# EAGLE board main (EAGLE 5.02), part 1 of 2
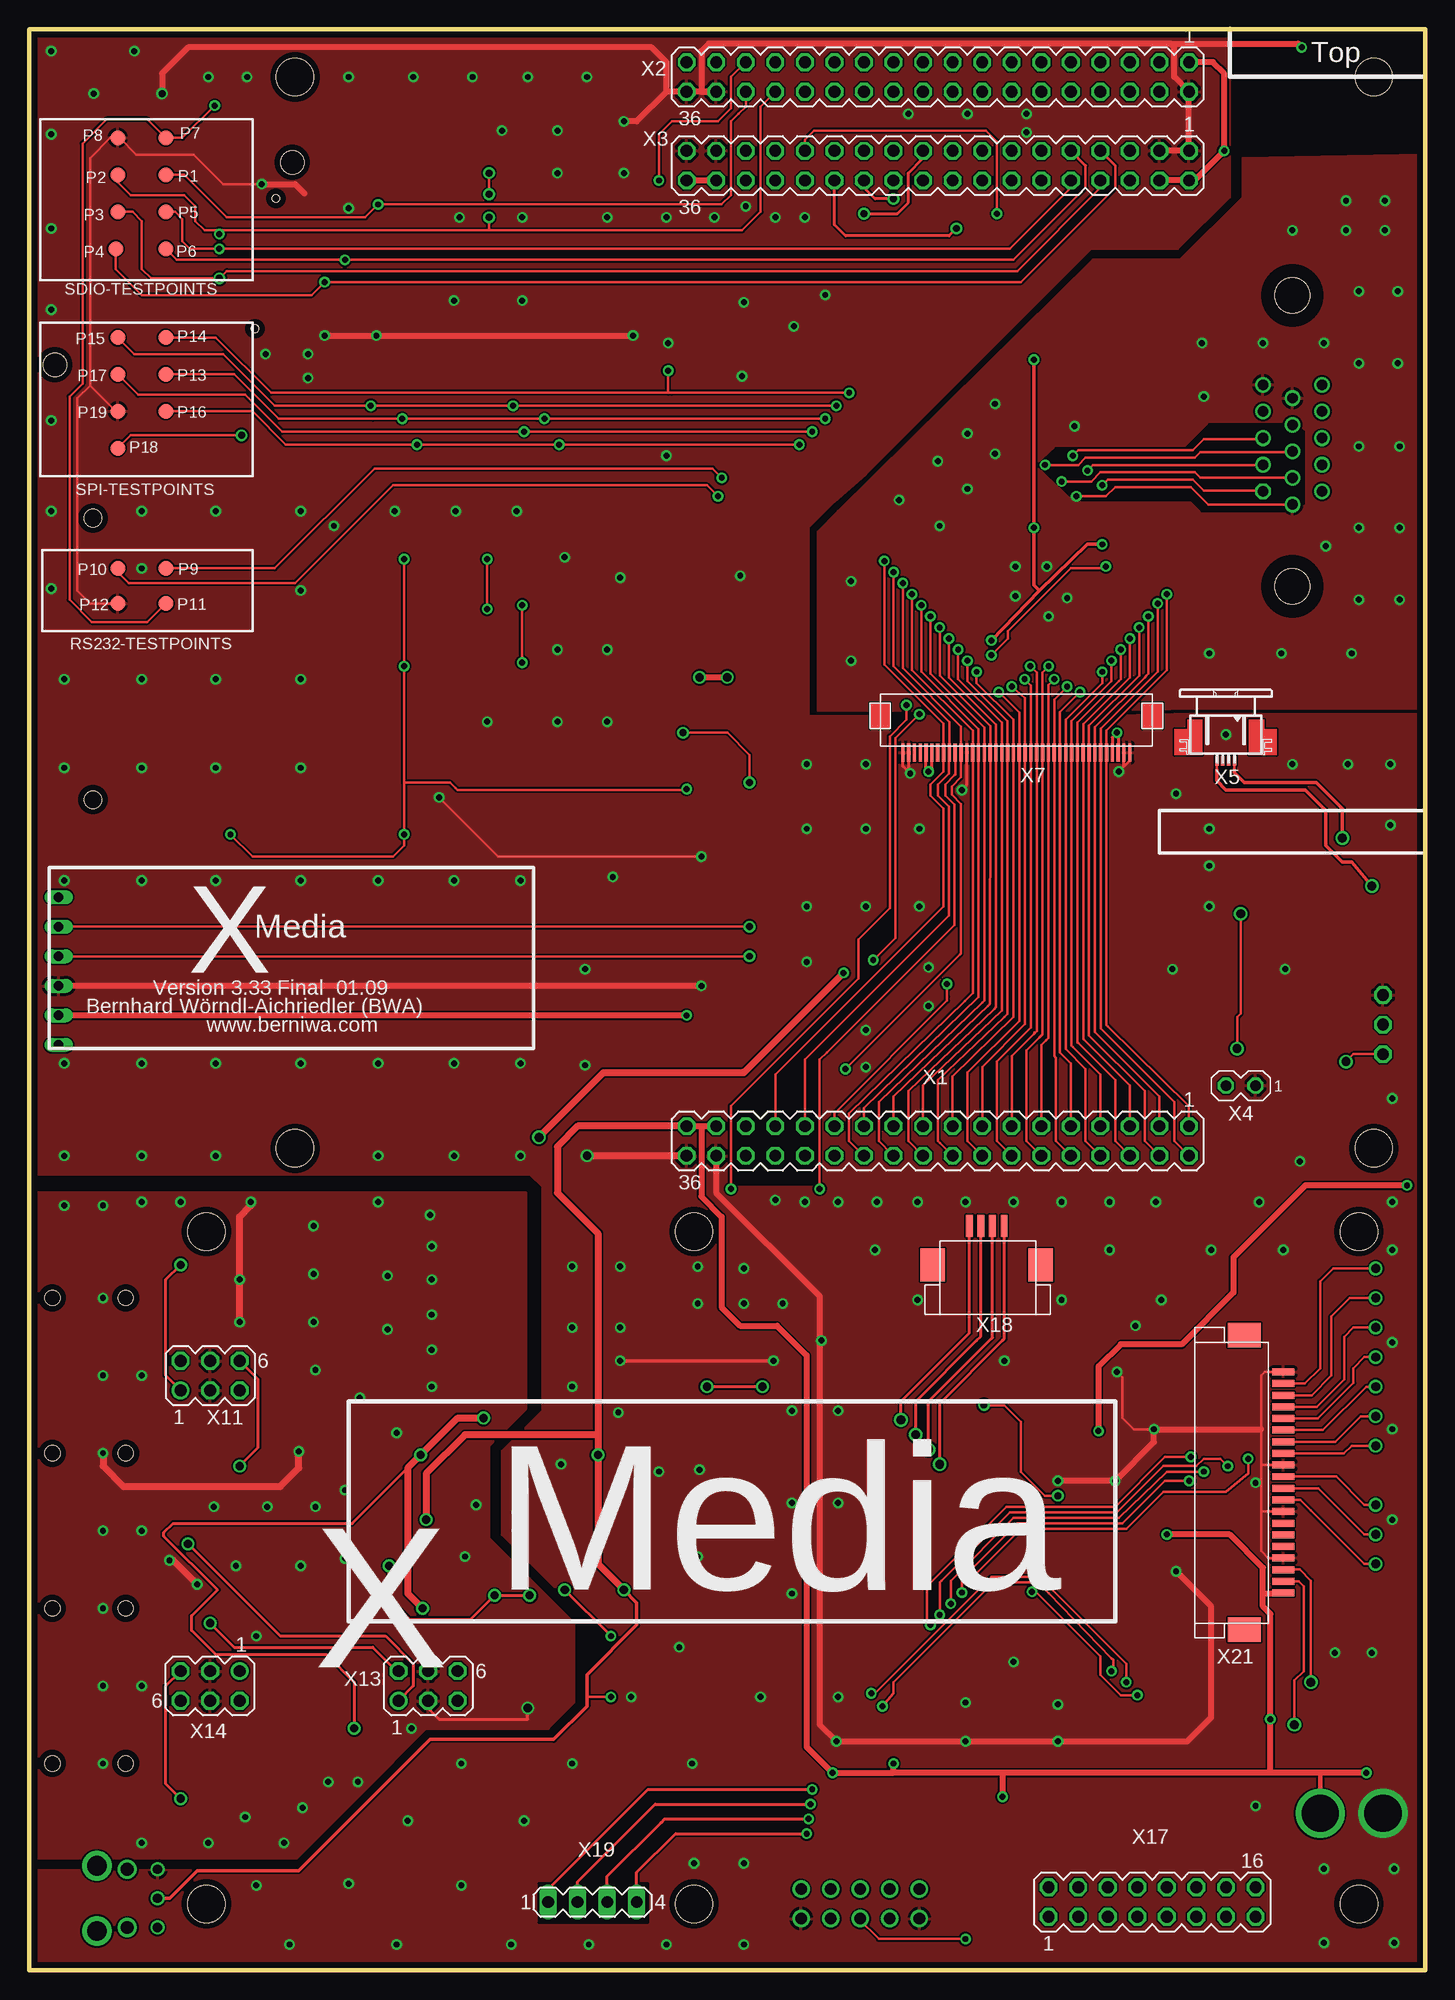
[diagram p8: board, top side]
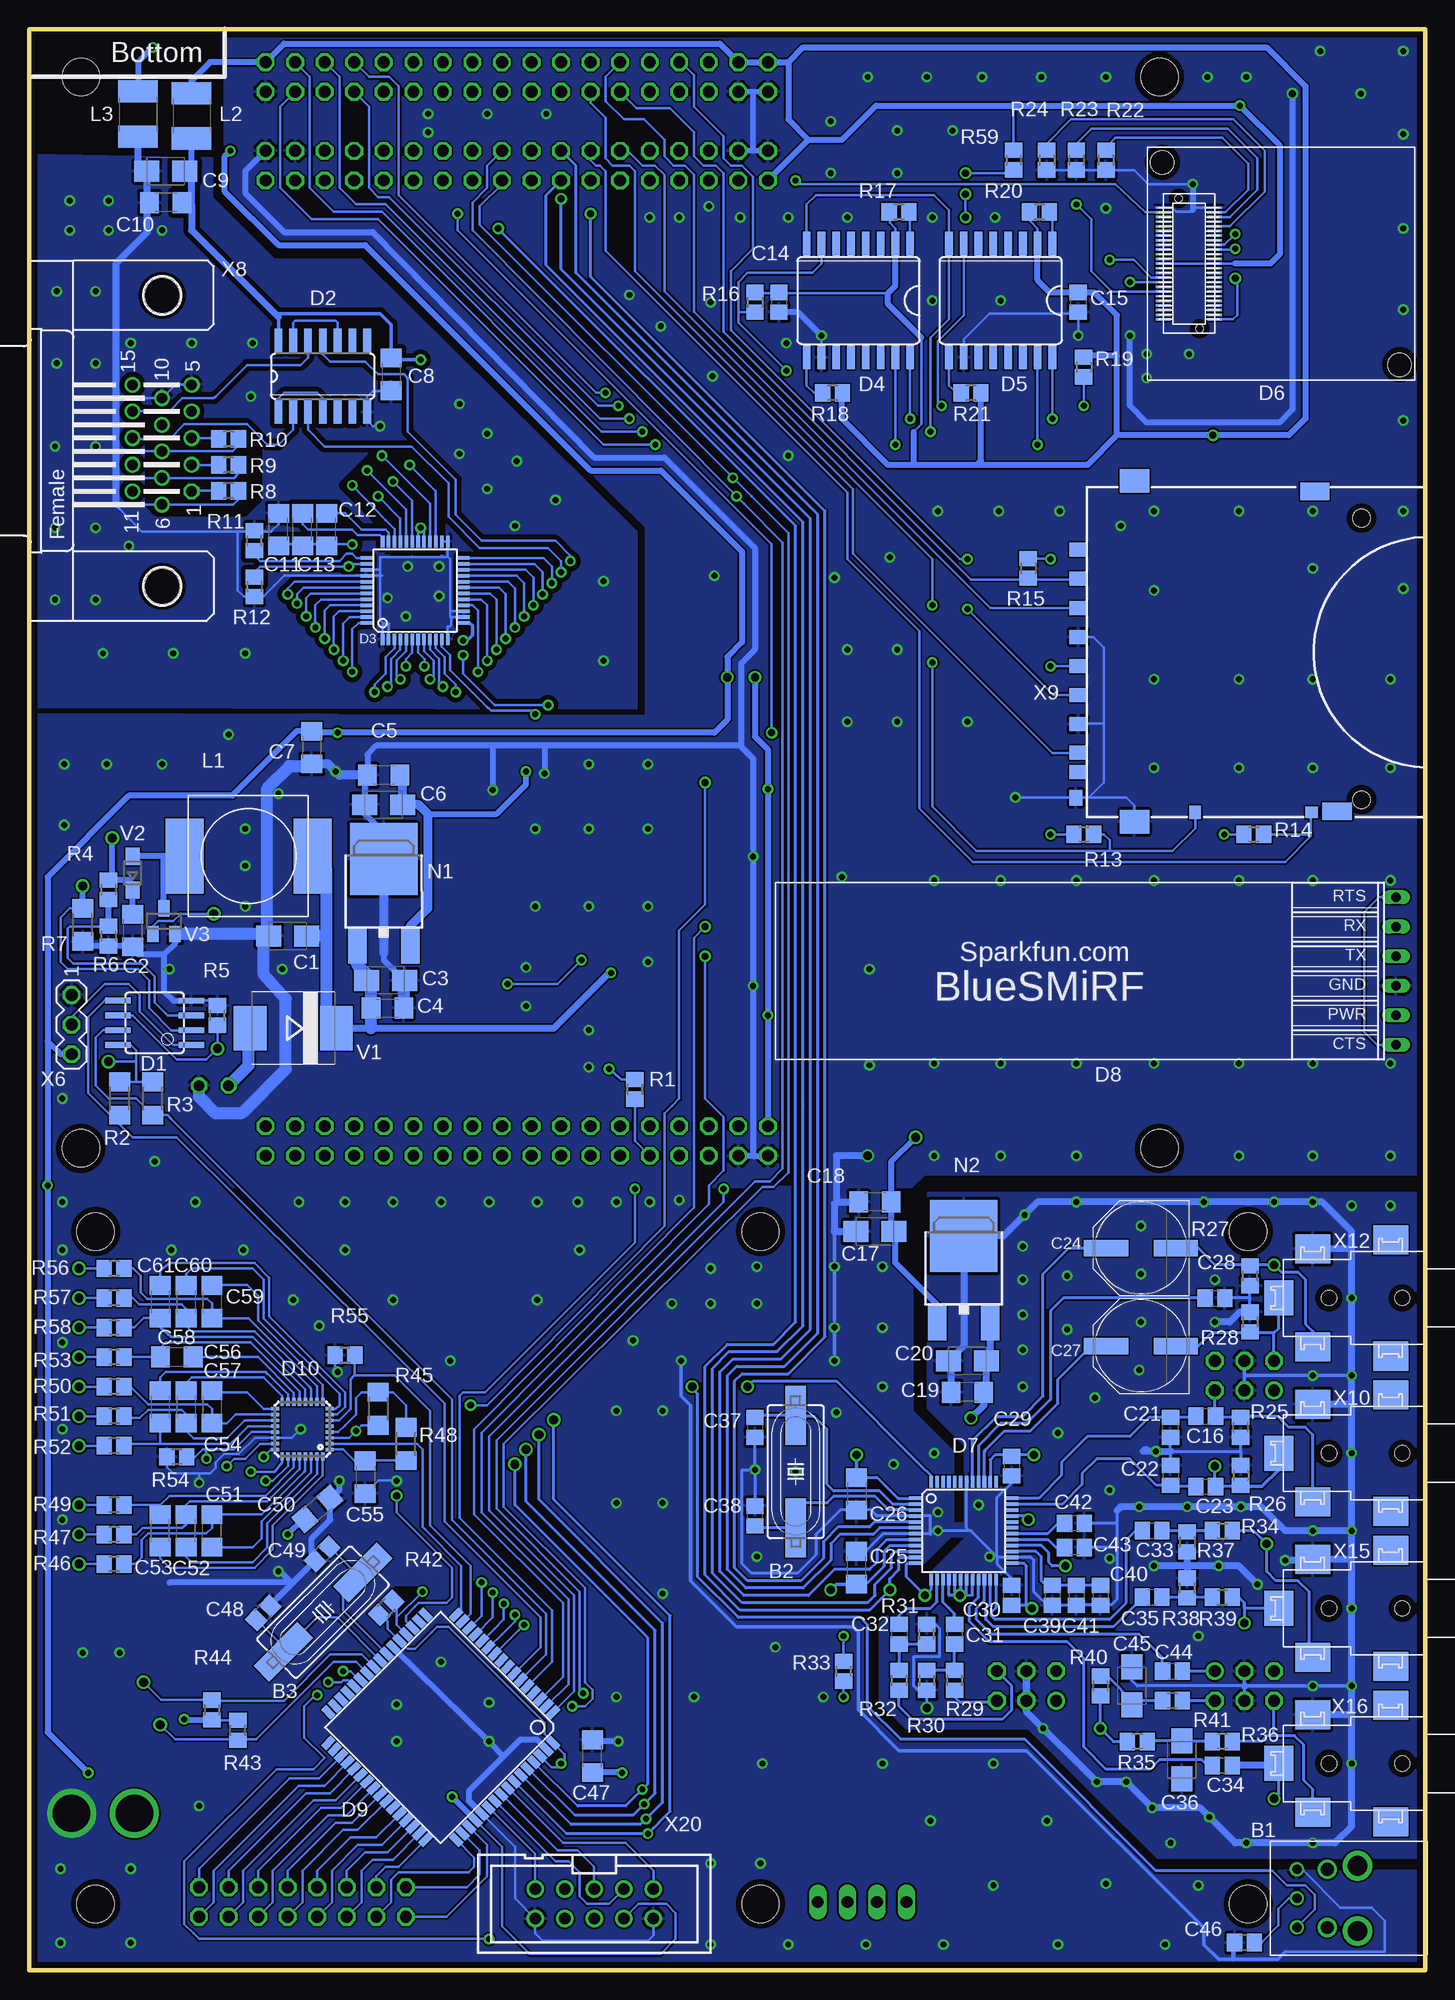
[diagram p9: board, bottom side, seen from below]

Size 120.02 x 166.83 mm. Coordinates in mm from the lower left corner, seen from the top.
Outline: 120,64.77 120,166.83 0,166.83 0,0 120.02,0 120.02,64.77
Copper layers (1+16): Top 0.035mm / dielectric 1.6mm / Bottom 0.035mm
Design rules "microtec *": minimum track width 6mil, minimum drill 0.4mm, track to track 6mil, track to pad 6mil, pad to pad 6mil, via to via 6mil, smd to smd 6mil, copper to edge 20mil, drill to drill 10mil, minimum pad ring 8mil, minimum via ring 8mil, stop-mask expansion 4mil, vias tented up to drill 18mil, thermal gap 10mil
Holes 3.2 mm at 115.57,162.72 22.86,162.72 22.86,70.64 115.57,70.64 15.24,63.5 15.24,5.71 114.3,63.5 114.3,5.71 57.15,5.71 57.15,63.5
tRestrict: area 43.8,4.1 to 53.2,7.5; area 86.7,125.4 to 109.5,132.9
bRestrict: area 86.4,31.7 to 88.6,32.9; area 100.5,125.4 to 109.5,132.9; area 84.8,121.4 to 92.9,130.7

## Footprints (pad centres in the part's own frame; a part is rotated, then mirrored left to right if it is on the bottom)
TOTX147PL = drill 0.8 round: 1 -2.5,-11.2; 2 0,-11.2; 3 2.5,-11.2 | drill 1.7 round: NC1 -2.8,-6; NC2 2.8,-6 | drill 1.1 round: NC3 -2.5,-8.6; NC4 2.5,-8.6
SM49 = smd 5.08 x 1.778: 1 -4.826,0; 2 4.826,0
HC49UP = smd 5.334 x 1.93: 1 -4.826,0; 2 4.826,0
B/3528-21W = smd 2.15 x 1.8: + 1.625,0; - -1.625,0
C1206 = smd 1.6 x 1.8: 1 -1.4,0; 2 1.4,0
C0805 = smd 1.3 x 1.5: 1 -0.85,0; 2 0.85,0
PANASONIC_E = smd 3.8 x 1.4: + 3,0; - -3,0
SOIC8 = smd 0.5 x 2.2: 1 -1.905,-3.154; 2 -0.645,-3.154; 3 0.625,-3.154; 4 1.895,-3.154; 5 1.905,3.154; 6 0.635,3.154; 7 -0.635,3.154; 8 -1.905,3.154
SO14 = smd 0.66 x 2.032: 1 -3.81,-3.073; 2 -2.54,-3.073; 3 -1.27,-3.073; 4 0,-3.073; 5 1.27,-3.073; 6 2.54,-3.073; 7 3.81,-3.073; 8 3.81,3.073; 9 2.54,3.073; 10 1.27,3.073; 11 0,3.073; 12 -1.27,3.073; 13 -2.54,3.073; 14 -3.81,3.073
TQFP48 = smd 1.016 x 0.305: 1 -4.191,2.794; 2 -4.191,2.286; 3 -4.191,1.778; 4 -4.191,1.27; 5 -4.191,0.762; 6 -4.191,0.254; 7 -4.191,-0.254; 8 -4.191,-0.762; 9 -4.191,-1.27; 10 -4.191,-1.778; 11 -4.191,-2.286; 12 -4.191,-2.794; 25 4.191,-2.794; 26 4.191,-2.286; 27 4.191,-1.778; 28 4.191,-1.27; 29 4.191,-0.762; 30 4.191,-0.254; 31 4.191,0.254; 32 4.191,0.762; 33 4.191,1.27; 34 4.191,1.778; 35 4.191,2.286; 36 4.191,2.794 | smd 0.305 x 1.016: 13 -2.794,-4.191; 14 -2.286,-4.191; 15 -1.778,-4.191; 16 -1.27,-4.191; 17 -0.762,-4.191; 18 -0.254,-4.191; 19 0.254,-4.191; 20 0.762,-4.191; 21 1.27,-4.191; 22 1.778,-4.191; 23 2.286,-4.191; 24 2.794,-4.191; 37 2.794,4.191; 38 2.286,4.191; 39 1.778,4.191; 40 1.27,4.191; 41 0.762,4.191; 42 0.254,4.191; 43 -0.254,4.191; 44 -0.762,4.191; 45 -1.27,4.191; 46 -1.778,4.191; 47 -2.286,4.191; 48 -2.794,4.191
SO16L = smd 0.66 x 2.032: 1 -4.445,-4.902; 2 -3.175,-4.902; 3 -1.905,-4.902; 4 -0.635,-4.902; 5 0.635,-4.902; 6 1.905,-4.902; 7 3.175,-4.902; 8 4.445,-4.902; 9 4.445,4.902; 10 3.175,4.902; 11 1.905,4.902; 12 0.635,4.902; 13 -0.635,4.902; 14 -1.905,4.902; 15 -3.175,4.902; 16 -4.445,4.902
XG-182M = smd 0.203 x 1.27: P$1 4.8,-2.2; P$2 4.4,-2.2; P$3 4,-2.2; P$4 3.6,-2.2; P$5 3.2,-2.2; P$6 2.8,-2.2; P$7 2.4,-2.2; P$8 2,-2.2; P$9 1.6,-2.2; P$10 1.2,-2.2; P$11 0.8,-2.2; P$12 0.4,-2.2; P$13 0,-2.2; P$14 -0.4,-2.2; P$15 -0.8,-2.2; P$16 -1.2,-2.2; P$17 -1.6,-2.2; P$18 -2,-2.2; P$19 -2.4,-2.2; P$20 -2.8,-2.2; P$21 -3.2,-2.2; P$22 -3.6,-2.2; P$23 -4,-2.2; P$24 -4.4,-2.2; P$25 -4.8,-2.2; P$26 -4.8,2.2; P$27 -4.4,2.2; P$28 -4,2.2; P$29 -3.6,2.2; P$30 -3.2,2.2; P$31 -2.8,2.2; P$32 -2.4,2.2; P$33 -2,2.2; P$34 -1.6,2.2; P$35 -1.2,2.2; P$36 -0.8,2.2; P$37 -0.4,2.2; P$38 0,2.2; P$39 0.4,2.2; P$40 0.8,2.2; P$41 1.2,2.2; P$42 1.6,2.2; P$43 2,2.2; P$44 2.4,2.2; P$45 2.8,2.2; P$46 3.2,2.2; P$47 3.6,2.2; P$48 4,2.2; P$49 4.4,2.2; P$50 4.8,2.2 | hole 0.65: 5.6,0.9; -5.6,-0.9 | hole 2: -8.7,-18.1; 8.7,2.3
BLUE_SMIRF_SOCKET = drill 0.813 long: CTS -6.35,-8.89; GND -1.27,-8.89; PWR -3.81,-8.89; RTS 6.35,-8.89; RX 3.81,-8.89; TX 1.27,-8.89
TQFP64 = smd 1.194 x 0.61: 1 -7.76,5.905; 2 -7.76,5.118; 3 -7.76,4.331; 4 -7.76,3.543; 5 -7.76,2.756; 6 -7.76,1.968; 7 -7.76,1.181; 8 -7.76,0.394; 9 -7.76,-0.394; 10 -7.76,-1.181; 11 -7.76,-1.968; 12 -7.76,-2.756; 13 -7.76,-3.543; 14 -7.76,-4.331; 15 -7.76,-5.118; 16 -7.76,-5.905; 33 7.76,-5.905; 34 7.76,-5.118; 35 7.76,-4.331; 36 7.76,-3.543; 37 7.76,-2.756; 38 7.76,-1.968; 39 7.76,-1.181; 40 7.76,-0.394; 41 7.76,0.394; 42 7.76,1.181; 43 7.76,1.968; 44 7.76,2.756; 45 7.76,3.543; 46 7.76,4.331; 47 7.76,5.118; 48 7.76,5.905 | smd 0.61 x 1.194: 17 -5.905,-7.76; 18 -5.118,-7.76; 19 -4.331,-7.76; 20 -3.543,-7.76; 21 -2.756,-7.76; 22 -1.968,-7.76; 23 -1.181,-7.76; 24 -0.394,-7.76; 25 0.394,-7.76; 26 1.181,-7.76; 27 1.968,-7.76; 28 2.756,-7.76; 29 3.543,-7.76; 30 4.331,-7.76; 31 5.118,-7.76; 32 5.905,-7.76; 49 5.905,7.76; 50 5.118,7.76; 51 4.331,7.76; 52 3.543,7.76; 53 2.756,7.76; 54 1.968,7.76; 55 1.181,7.76; 56 0.394,7.76; 57 -0.394,7.76; 58 -1.181,7.76; 59 -1.968,7.76; 60 -2.756,7.76; 61 -3.543,7.76; 62 -4.331,7.76; 63 -5.118,7.76; 64 -5.905,7.76
MLF32 = smd 0.7 x 0.29: 1 -2.35,1.75; 2 -2.35,1.25; 3 -2.35,0.75; 4 -2.35,0.25; 5 -2.35,-0.25; 6 -2.35,-0.75; 7 -2.35,-1.25; 8 -2.35,-1.75; 17 2.35,-1.75; 18 2.35,-1.25; 19 2.35,-0.75; 20 2.35,-0.25; 21 2.35,0.25; 22 2.35,0.75; 23 2.35,1.25; 24 2.35,1.75 | smd 0.29 x 0.7: 9 -1.75,-2.35; 10 -1.25,-2.35; 11 -0.75,-2.35; 12 -0.25,-2.35; 13 0.25,-2.35; 14 0.75,-2.35; 15 1.25,-2.35; 16 1.75,-2.35; 25 1.75,2.35; 26 1.25,2.35; 27 0.75,2.35; 28 0.25,2.35; 29 -0.25,2.35; 30 -0.75,2.35; 31 -1.25,2.35; 32 -1.75,2.35
EPCOS10X10 = smd 3.251 x 6.452: P$1 -0.4,5.2; P$2 10.6,5.2
L1812 = smd 1.9 x 3.4: 1 -1.95,0; 2 1.95,0
DPAK = smd 1.6 x 3: 1 -2.28,-4.04; 3 2.28,-4.04 | smd 5.791 x 6.198: 4 0,3.427
B1,27 = smd 1.27 x 1.27: PP 0,0
R0805 = smd 1.3 x 1.5: 1 -0.85,0; 2 0.85,0
R1206 = smd 1.6 x 1.803: 1 -1.422,0; 2 1.422,0
SMC = smd 2.8 x 3.8: A 3.7,0; C -3.7,0
SOD323-W = smd 1.5 x 1.2: A 1.45,0; C -1.45,0
SOT23 = smd 1 x 1.4: 1 -0.95,-1.1; 2 0.95,-1.1; 3 0,1.1
MA18-2 = drill 1.016 octagon: 1 -21.59,-1.27; 2 -21.59,1.27; 3 -19.05,-1.27; 4 -19.05,1.27; 5 -16.51,-1.27; 6 -16.51,1.27; 7 -13.97,-1.27; 8 -13.97,1.27; 9 -11.43,-1.27; 10 -11.43,1.27; 11 -8.89,-1.27; 12 -8.89,1.27; 13 -6.35,-1.27; 14 -6.35,1.27; 15 -3.81,-1.27; 16 -3.81,1.27; 17 -1.27,-1.27; 18 -1.27,1.27; 19 1.27,-1.27; 20 1.27,1.27; 21 3.81,-1.27; 22 3.81,1.27; 23 6.35,-1.27; 24 6.35,1.27; 25 8.89,-1.27; 26 8.89,1.27; 27 11.43,-1.27; 28 11.43,1.27; 29 13.97,-1.27; 30 13.97,1.27; 31 16.51,-1.27; 32 16.51,1.27; 33 19.05,-1.27; 34 19.05,1.27; 35 21.59,-1.27; 36 21.59,1.27
02P = drill 0.914 octagon: 1 -1.27,0; 2 1.27,0
52745-0490 = smd 0.3 x 0.8: 1 0.52,-0.04; 2 1.02,-0.04; 3 1.52,-0.04; 4 2.02,-0.04
MA03-1 = drill 1.016 octagon: 1 -2.54,0; 2 0,0; 3 2.54,0
ZIF40 = smd 0.279 x 1.524: 1 0.25,0.75; 2 0.75,0.75; 3 1.25,0.75; 4 1.75,0.75; 5 2.25,0.75; 6 2.75,0.75; 7 3.25,0.75; 8 3.75,0.75; 9 4.25,0.75; 10 4.75,0.75; 11 5.25,0.75; 12 5.75,0.75; 13 6.25,0.75; 14 6.75,0.75; 15 7.25,0.75; 16 7.75,0.75; 17 8.25,0.75; 18 8.75,0.75; 19 9.25,0.75; 20 9.75,0.75; 21 10.25,0.75; 22 10.75,0.75; 23 11.25,0.75; 24 11.75,0.75; 25 12.25,0.75; 26 12.75,0.75; 27 13.25,0.75; 28 13.75,0.75; 29 14.25,0.75; 30 14.75,0.75; 31 15.25,0.75; 32 15.75,0.75; 33 16.25,0.75; 34 16.75,0.75; 35 17.25,0.75; 36 17.75,0.75; 37 18.25,0.75; 38 18.75,0.75; 39 19.25,0.75; 40 19.75,0.75
HDF15H = drill 0.9 octagon: 1 4.329,2.54 | drill 0.9 round: 2 2.043,2.54; 3 -0.243,2.54; 4 -2.529,2.54; 5 -4.815,2.54; 6 5.472,0; 7 3.186,0; 8 0.9,0; 9 -1.386,0; 10 -3.672,0; 11 4.329,-2.54; 12 2.043,-2.54; 13 -0.243,-2.54; 14 -2.529,-2.54; 15 -4.815,-2.54 | hole 3: -12.5,0; 12.5,0
SD-MMC_SOCKET-PP = smd 1.2 x 1.5: 1 6.88,29.85; 2 4.38,29.85; 3 1.88,29.85; 4 -0.62,29.85; 5 -3.12,29.85; 6 -5.62,29.85; 7 -8.04,29.85; 8 -9.728,29.87; 9 9.38,29.85 | smd 1.5 x 2.5: 12 -13.1,7.6; 13 14.402,9.525 | smd 2 x 2.5: 14 -14,25; 15 15.3,25 | smd 1 x 1.05: CD -13.18,9.8 | smd 1.3 x 1.1: SW -11.938,30.048 | smd 1.15 x 1: WP -13.18,19.8 | hole 1.5: -12.1,5.5; 12.1,5.5
1503_03 = smd 2.5 x 3: GND -4.2,-9.7; NC1 -5,-3; NC2 5,-3; R 4.2,-9.7 | smd 3 x 2.5: L 0,-12.6 | hole 1.3: 0,-2; 0,-8.3
MA03-2 = drill 1.016 round: 1 -2.54,-1.27 | drill 1.016 octagon: 2 -2.54,1.27; 3 0,-1.27; 4 0,1.27; 5 2.54,-1.27; 6 2.54,1.27
MA08-2 = drill 1.016 octagon: 1 -8.89,-1.27; 2 -8.89,1.27; 3 -6.35,-1.27; 4 -6.35,1.27; 5 -3.81,-1.27; 6 -3.81,1.27; 7 -1.27,-1.27; 8 -1.27,1.27; 9 1.27,-1.27; 10 1.27,1.27; 11 3.81,-1.27; 12 3.81,1.27; 13 6.35,-1.27; 14 6.35,1.27; 15 8.89,-1.27; 16 8.89,1.27
FPC-4-1MM = smd 0.6 x 1.9: P$1 0,0; P$2 1,0; P$3 2,0; P$4 3,0 | smd 2.1 x 2.8: P$21 6.15,-3.35; P$22 -3.15,-3.35
MA04-1 = drill 1.016 long: 1 -3.81,0; 2 -1.27,0; 3 1.27,0; 4 3.81,0
PAK100/2500-10 = drill 1 pad 1.422 round: 1 -5.08,-1.27; 2 -5.08,1.27; 3 -2.54,-1.27; 4 -2.54,1.27; 5 0,-1.27; 6 0,1.27; 7 2.54,-1.27; 8 2.54,1.27; 9 5.08,-1.27; 10 5.08,1.27
FPC-20-1MM = smd 0.6 x 1.9: P$1 0,0; P$2 1,0; P$3 2,0; P$4 3,0; P$5 4,0; P$6 5,0; P$7 6,0; P$8 7,0; P$9 8,0; P$10 9,0; P$11 10,0; P$12 11,0; P$13 12,0; P$14 13,0; P$15 14,0; P$16 15,0; P$17 16,0; P$18 17,0; P$19 18,0; P$20 19,0 | smd 2.1 x 2.8: P$21 22.15,-3.35; P$22 -3.15,-3.35

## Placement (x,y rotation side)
B1  TOTX147PL  [TOTX147PL]  -0.16,6.19 270 bottom
B2  24.576MHz  [SM49]  54.13,42.86 270 bottom
B3  8MHz  [HC49UP]  94.75,30.8 45 bottom
C1  10u/16V  [B/3528-21W]  97.79,88.9 0 bottom
C2  4.7u  [C1206]  111.12,89.38 270 bottom
C3  10u/16V  [B/3528-21W]  89.38,85.09 180 bottom
C4  100n  [C1206]  89.22,82.71 0 bottom
C5  100n  [C1206]  89.54,102.71 180 bottom
C6  10u/16V  [B/3528-21W]  89.53,100.17 0 bottom
C7  100n  [C1206]  95.73,105.09 270 bottom
C8  100n  [C1206]  88.9,137.16 270 bottom
C9  10u/16V  [B/3528-21W]  108.27,154.62 0 bottom
C10  100n  [C1206]  108.27,151.92 180 bottom
C11  100n  [C1206]  98.58,123.83 90 bottom
C12  100n  [C1206]  94.46,123.83 90 bottom
C13  100n  [C1206]  96.52,123.83 90 bottom
C14  100n  [C0805]  55.56,143.35 270 bottom
C15  100n  [C0805]  29.84,143.35 270 bottom
C16  1u  [C0805]  18.89,47.62 0 bottom
C17  10u/16V  [B/3528-21W]  47.31,63.5 0 bottom
C18  100n  [C1206]  47.31,66.04 180 bottom
C19  100n  [C1206]  39.37,49.69 180 bottom
C20  10u/16V  [B/3528-21W]  39.37,52.39 0 bottom
C21  1n  [C0805]  21.91,46.67 90 bottom
C22  1n  [C0805]  21.91,42.54 270 bottom
C23  1u  [C0805]  18.89,41.59 0 bottom
C24  220u  [PANASONIC_E]  24.45,62.07 180 bottom
C25  100n  [C1206]  48.89,34.61 90 bottom
C26  100n  [C1206]  48.9,40.96 270 bottom
C27  220u  [PANASONIC_E]  24.45,53.66 180 bottom
C28  1u  [C0805]  18.1,57.78 0 bottom
C29  100n  [C0805]  35.56,43.34 270 bottom
C30  100n  [C0805]  35.56,32.23 90 bottom
C31  1u  [C0805]  40.48,28.89 270 bottom
C32  1u  [C0805]  45.24,28.89 270 bottom
C33  1u  [C0805]  23.49,37.78 0 bottom
C34  1u  [C0805]  17.46,17.62 0 bottom
C35  1u  [C0805]  23.5,32.07 0 bottom
C36  10u/16V  [B/3528-21W]  20.95,18.1 90 bottom
C37  22p  [C0805]  57.63,46.67 270 bottom
C38  22p  [C0805]  57.63,39.05 90 bottom
C39  100n  [C0805]  32.07,32.23 270 bottom
C40  1u  [C0805]  27.94,32.23 270 bottom
C41  1u  [C0805]  30,32.23 270 bottom
C42  1n  [C0805]  30.16,38.42 180 bottom
C43  1n  [C0805]  30.16,36.35 180 bottom
C44  1u  [C0805]  21.75,25.72 0 bottom
C45  10u/16V  [B/3528-21W]  25.24,24.45 270 bottom
C46  100n  [C0805]  15.56,2.38 180 bottom
C47  100n  [C1206]  71.6,18.42 90 bottom
C48  22p  [C0805]  99.89,30.71 225 bottom
C49  22p  [C0805]  94.82,35.78 45 bottom
C50  100n  [C1206]  95.23,39.68 40 bottom
C51  22n  [C1206]  104.3,37.78 90 bottom
C52  22n  [C1206]  106.52,37.78 90 bottom
C53  22n  [C1206]  108.74,37.78 90 bottom
C54  4.7n  [C1206]  104.3,48.42 270 bottom
C55  100n  [C1206]  91.12,42.39 270 bottom
C56  4.7n  [C1206]  106.52,48.42 270 bottom
C57  4.7n  [C1206]  108.74,48.42 270 bottom
C58  4.7n  [C1206]  107.32,52.71 180 bottom
C59  4.7n  [C1206]  104.3,57.47 270 bottom
C60  4.7n  [C1206]  106.52,57.47 270 bottom
C61  4.7n  [C1206]  108.74,57.47 270 bottom
D1  ATTINY45S  [SOIC8]  109.22,81.44 90 bottom
D2  74LVC04D  [SO14]  94.77,137 0 bottom
D3  ADV7125  [TQFP48]  86.84,118.59 90 bottom
D4  Spansion 128Mbit Serial NOR Flash  [SO16L]  48.74,143.51 180 bottom
D5  Spansion 128Mbit Serial NOR Flash  [SO16L]  36.51,143.51 180 bottom
D6  XG-182M  [XG-182M]  20.32,146.69 90 bottom
D7  CS4202  [TQFP48]  39.69,37.78 0 bottom
D8  BlueSMiRF  [BLUE_SMIRF_SOCKET]  11.43,85.88 90 bottom
D9  ATMEGA1281V-8AI  [TQFP64]  84.63,20.88 225 bottom
D10  QT1106  [MLF32]  96.52,46.51 180 bottom
DRILEGEND  [DRILEGEND]  not placed on the board
L1  1000uH  [EPCOS10X10]  96.04,100.96 180 bottom
L2  BLM41PG750SN1L  [L1812]  106.05,159.38 270 bottom
L3  BLM41PG750SN1L  [L1812]  110.65,159.54 270 bottom
MEASURE  [MEASURE]  0,0 0 top
N1  MC78M05CDT  [DPAK]  89.53,92.07 0 bottom
N2  MC78M05CDT  [DPAK]  39.69,59.69 0 bottom
P1  SDIO-CLK  [B1,27]  11.75,154.31 0 top
P2  SDIO-CMD1  [B1,27]  7.62,154.31 0 top
P3  SDIO-D4  [B1,27]  7.62,151.13 0 top
P4  SDIO-D5  [B1,27]  7.46,147.96 0 top
P5  SDIO-D6  [B1,27]  11.75,151.13 0 top
P6  SDIO-D7  [B1,27]  11.75,147.96 0 top
P7  +3.3V  [B1,27]  11.75,157.48 0 top
P8  GND  [B1,27]  7.62,157.48 0 top
P9  BOARD_TX  [B1,27]  11.75,120.49 0 top
P10  BOARD_RX  [B1,27]  7.62,120.49 0 top
P11  +3.3V  [B1,27]  11.75,117.47 0 top
P12  GND  [B1,27]  7.62,117.47 0 top
P13  SPI0-SCK  [B1,27]  11.75,137.16 0 top
P14  SPI0-CS1  [B1,27]  11.75,140.34 0 top
P15  SPI0-CS2  [B1,27]  7.62,140.33 0 top
P16  SPI0-MOSI  [B1,27]  11.75,133.98 0 top
P17  SPI0-MISO  [B1,27]  7.62,137.16 0 top
P18  +3.3V  [B1,27]  7.62,130.81 0 top
P19  GND  [B1,27]  7.62,133.99 0 top
R1  47R  [R0805]  67.95,75.72 90 bottom
R2  5k6  [R1206]  112.24,74.93 270 bottom
R3  5k6  [R1206]  109.38,74.93 270 bottom
R4  39k  [R0805]  113.19,92.87 270 bottom
R5  10k  [R0805]  103.82,82.07 90 bottom
R6  2k2  [R0805]  113.19,88.9 270 bottom
R7  22R  [R1206]  115.41,89.85 270 bottom
R8  75R  [R0805]  102.87,127.16 180 bottom
R9  75R  [R0805]  102.87,129.38 180 bottom
R10  75R  [R0805]  102.87,131.6 180 bottom
R11  560R  [R0805]  100.65,122.87 90 bottom
R12  100k  [R0805]  100.65,118.9 270 bottom
R13  100k  [R0805]  29.37,97.63 0 bottom
R14  100k  [R0805]  14.76,97.63 0 bottom
R15  100k  [R0805]  34.13,120.49 270 bottom
R16  100k  [R0805]  57.63,143.35 270 bottom
R17  100k  [R0805]  45.24,151.13 0 bottom
R18  100k  [R0805]  50.96,135.57 180 bottom
R19  100k  [R0805]  29.37,137.8 270 bottom
R20  100k  [R0805]  33.18,151.13 0 bottom
R21  100k  [R0805]  39.05,135.57 180 bottom
R22  100k  [R0805]  27.46,155.57 270 bottom
R23  100k  [R0805]  30,155.57 270 bottom
R24  100k  [R0805]  32.54,155.57 270 bottom
R25  220k  [R0805]  15.88,46.67 90 bottom
R26  220k  [R0805]  15.88,42.54 270 bottom
R27  10k  [R0805]  15.08,59.69 90 bottom
R28  10k  [R0805]  15.08,55.72 270 bottom
R29  6k8  [R0805]  40.48,24.92 270 bottom
R30  6k8  [R0805]  42.86,24.92 270 bottom
R31  6k8  [R0805]  42.86,28.89 90 bottom
R32  6k8  [R0805]  45.24,24.92 270 bottom
R33  100k  [R0805]  50.01,25.72 90 bottom
R34  6k8  [R0805]  17.46,37.78 0 bottom
R35  1k5  [R0805]  24.77,19.68 180 bottom
R36  2k2  [R0805]  17.46,19.68 180 bottom
R37  6k8  [R0805]  20.48,36.83 270 bottom
R38  6k8  [R0805]  20.48,32.86 90 bottom
R39  6k8  [R0805]  17.46,32.07 0 bottom
R40  1k5  [R0805]  27.94,24.45 270 bottom
R41  2k2  [R0805]  21.75,23.18 180 bottom
R42  100k  [R0805]  89.33,31.16 45 bottom
R43  2k2  [R0805]  102.08,20.64 90 bottom
R44  2k2  [R0805]  104.3,22.38 270 bottom
R45  12k  [R1206]  90.01,48.26 90 bottom
R46  10k  [R0805]  112.71,34.92 180 bottom
R47  10k  [R0805]  112.71,37.46 180 bottom
R48  22k  [R1206]  87.63,45.24 270 bottom
R49  10k  [R0805]  112.71,40 180 bottom
R50  10k  [R0805]  112.71,50.17 180 bottom
R51  10k  [R0805]  112.71,47.62 180 bottom
R52  10k  [R0805]  112.71,45.08 180 bottom
R53  10k  [R0805]  112.71,52.7 180 bottom
R54  100k  [R0805]  107.32,44.13 180 bottom
R55  100k  [R0805]  92.87,52.86 180 bottom
R56  10k  [R0805]  112.71,60.33 180 bottom
R57  10k  [R0805]  112.71,57.78 180 bottom
R58  10k  [R0805]  112.71,55.24 180 bottom
R59  100k  [R0805]  35.4,155.57 270 bottom
V1  MBRS340T3G  [SMC]  97.31,80.96 180 bottom
V2  BAT54J  [SOD323-W]  111.12,94.3 90 bottom
V3  VN7002  [SOT23]  108.43,90.17 0 bottom
X1  NGW100-J7-LCD  [MA18-2]  78.11,71.28 180 top
X2  NGW100-J5-EX2  [MA18-2]  78.11,162.72 180 top
X3  NGW100-J6-EX1  [MA18-2]  78.11,155.1 180 top
X4  Supply  [02P]  104.14,76.04 180 top
X5  VLED  [52745-0490]  104.11,103.92 180 top
X6  DW  [MA03-1]  116.36,81.28 270 bottom
X7  LCD-DISPLAY  [ZIF40]  74.85,103.9 0 top
X8  VGA  [HDF15H]  108.58,131.44 270 bottom
X9  SD-Card  [SD-MMC_SOCKET-PP]  0,112.71 90 bottom
X10  Line Out  [1503_03]  0,44.45 270 bottom
X11  Audio Out  [MA03-2]  15.56,51.12 0 top
X12  Headphone Out  [1503_03]  0,57.78 270 bottom
X13  Audio In  [MA03-2]  34.29,24.45 0 top
X14  Mic In  [MA03-2]  15.56,24.45 180 top
X15  Line In  [1503_03]  0,31.12 270 bottom
X16  Mic1 In  [1503_03]  0,17.78 270 bottom
X17  Board GPIO  [MA08-2]  96.52,5.87 0 top
X18  Touchscreen  [FPC-4-1MM]  80.8,63.98 0 top
X19  BOARD_AD  [MA04-1]  48.42,5.87 0 top
X20  JTAG  [PAK100/2500-10]  71.44,5.71 180 bottom
X21  Capacitive Panel  [FPC-20-1MM]  107.79,51.43 270 top

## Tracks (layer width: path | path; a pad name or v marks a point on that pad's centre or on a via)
!AUDIO-RESET  (via drill 0.51, 0.6, 0.7)
  Top 0.254: v50.01,28.73 v46.04,32.7 | X3.26 69.22,150.02 70.17,149.07 79.06,149.07 79.61,149.62 | 79.61,149.62 v79.69,149.7 | v79.69,149.7 | v79.69,149.7 79.61,149.62
  Bottom 0.203: v50.01,28.73 | R33.2 v50.01,28.73 | v50.01,28.73
  Bottom 0.254: D7.11 45.15,35.5 45.24,35.4 45.24,34.45 46.04,33.65 v46.04,32.7 47.78,30.96 58.9,30.96 61.91,33.97 61.91,51.91 60.01,53.82 56.04,53.82 54.13,55.72 54.13,124.14 v79.69,149.7
!BOARD_RESET  (via drill 0.51)
  Top 0.203: v86.2,32.54 86.52,32.54 92.08,26.99 92.08,25.4 93.82,23.65 v95.25,23.65 | 71.28,4.44 | X20.6 71.28,4.44 | 71.28,4.44 73.03,2.7 v80.49,2.7
  Bottom 0.203: R42.2 88.42,31.43 88.42,29.69 | D9.20 88.42,29.69 | 88.42,29.69 88.42,30.32 v86.2,32.54 | v95.25,23.65 95.41,23.65 96.36,22.7 96.36,20 94.61,18.26 95.57,17.3 98.74,17.3 106.68,9.37 106.68,3.97 105.89,3.17 | 105.89,3.17 | 105.89,3.17 105.41,2.7 v80.49,2.7
!CAP_CHANGE
  Bottom 0.203: D10.6 93.39,47.26 92.39,48.26 92.39,50.8 92.08,51.12 | 92.08,51.12 88.58,51.12 85.57,48.1 85.57,38.26 82.07,34.77 82.07,30.64 82.72,29.99 D9.15 | 92.08,51.12 92.02,51.17 R55.1
!CAP_RESET
  Bottom 0.203: D10.2 86.7,45.26 86.68,45.24 86.2,44.77 86.2,38.1 86.04,37.94 | 86.04,37.94 82.87,34.77 82.87,30.96 83.32,30.5 | 83.32,30.5 83.34,30.48 | D9.16 83.32,30.5 | 86.04,37.94
!CAP_SS  (via drill 0.51)
  Top 0.203: v99.85,44.13 97.63,44.13 93.34,39.85 83.98,39.85 77.15,33.02 77.15,30 v77.47,29.69
  Bottom 0.203: D10.24 99.22,44.76 99.69,44.29 | v99.85,44.13 99.69,44.29 | 99.69,44.29 | v99.85,44.13 | v99.85,44.13 99.69,44.29 | 77.95,29.21 v77.47,29.69 | 77.95,29.21 | 79.95,27.2 77.95,29.21
  Bottom 0.305: D9.10 79.95,27.2
!SD_WP  (via drill 0.51)
  Top 0.203: v42.39,112.39 v42.39,117.32
  Bottom 0.203: X9.WP 19.8,98.15 21.75,96.2 27.15,96.2 | 27.15,96.2 38.58,96.2 42.39,100.01 v42.39,112.39 | v42.39,117.32 42.39,120.49 42.39,121.28 65.41,144.3 65.41,144.46 65.41,154.3 66.2,155.1 67.31,155.1 68.58,156.37 X3.25 | R13.2 27.62,97.63 27.15,97.15 27.15,96.2 | X3.25
+3.3V  (via drill 0.51, 0.6, 0.7, 0.76, 3.2)
  Top 0.203: 47.94,23.49 v50.01,23.49 | v32.23,121.28 v32.23,112.08 32.23,102.08 | v17.3,97.63 19.21,95.73 31.27,95.73 32.23,96.68 v32.23,97.63 32.23,102.08 | 32.23,102.08 36.2,102.08 36.67,101.6 | 36.67,101.6 | 36.67,101.6 36.83,101.44 56.52,101.44 | 56.52,101.44 56.59,101.52 | v15.95,160.26 13.18,157.48 P7.PP 10.16,159.07 6.67,159.07 4.6,157 4.6,136.37 3.49,135.25 3.49,117.79 5.4,115.89 10.16,115.89 P11.PP | v18.26,131.92 8.73,131.92 P18.PP | v91.92,46.35 | v91.92,46.35 | X6.3 113.82,78.74 v113.19,78.1 | v56.52,101.52 56.52,101.44
  Top 0.254: X7.37 93.1,105.96 v93.5,106.36 93.6,106.27 X7.38
  Top 0.305: 48.9,45.88 48.9,46.04 | v51.12,32.7 52.23,31.59 52.23,29.69 47.94,25.4 47.94,23.49 47.94,22.7 45.09,19.84 34.45,19.84 23.18,8.57 14.45,8.57 12.06,6.19 B1.2
  Top 0.406: 110.97,16.99 v110.97,13.49
  Top 0.508: v60.01,111.12 v57.63,111.12 | 66.83,52.86 | 66.83,52.86 64.29,55.4 61.12,55.4 59.53,56.99 59.53,64.77 57.78,66.52 57.78,72.55 X1.35 X1.33 | 66.83,52.86 66.83,32.07 66.83,19.21 v69.06,16.99 74.3,16.99 | X3.34 | X3.36 X3.34 | X3.34 | X3.36 | X3.36 | v56.52,82.07 D8.PWR | X3.2 | X3.2 X3.4 | X3.2 | X3.2 100.17,153.83 v102.71,156.37 102.71,163.04 101.76,163.99 X2.1 | 83.66,16.99 74.3,16.99 | 83.66,16.99 v83.66,14.92 | 74.3,16.99 v74.3,17.78 | 106.68,16.99 83.66,16.99 | 106.68,16.99 v106.68,21.59 106.68,30.64 106.05,31.27 106.05,32.38 | X21.P$20 107.68,32.43 107.63,32.38 106.05,32.38 | v97.79,37.46 103.19,37.46 106.05,34.61 106.05,32.38 | v114.94,16.99 110.97,16.99 106.68,16.99 | v91.92,46.35 91.92,51.91 93.82,53.82 99.06,53.82 103.5,58.26 103.5,61.28 109.7,67.47 v118.43,67.47
  Top 0.61: v34.13,38.73 34.13,42.7 37.47,46.04 48.9,46.04 | v51.12,32.7 48.9,34.92 v48.9,44.29 48.9,45.88 48.9,63.34 45.4,66.83 45.4,70.8 47.15,72.55 X1.35
  Bottom 0.203: C46.1 14.13,2.38 12.64,3.87 12.64,5.29 11.75,6.19 B1.2 | 74.93,19.53 73.98,18.57 73.98,18.1 74.14,17.94 v74.3,17.78 74.61,17.46 75.09,17.46 D9.62 | D9.52 81.63,12.89 79.38,10.64 79.38,3.81 76.99,1.43 65.72,1.43 64.45,2.7 64.45,4.92 65.25,5.71 67.63,5.71 X20.4 | X20.4 | v50.01,23.49 R33.1 | v50.01,23.49 | D9.21 | D9.21 89.22,29.37 89.22,30 89.85,30.64 R42.1 | D9.64 74.93,19.53 | D9.21 | D9.21 87.47,27.62 86.84,27.62 85.41,29.05 | 85.41,29.05 | 85.41,29.05 84.93,29.53 83.98,29.53 75.72,21.27 75.72,20.32 74.93,19.53 | X9.4 29.99,112.09 30,112.08 v32.23,112.08 | R15.1 32.28,121.34 v32.23,121.28 | v32.23,97.63 R13.1 | v17.3,97.63 R14.1 | 18.26,146.68 | 18.26,146.68 D6.P$13 | 18.26,146.68 D6.P$38 16.35,146.68 | 18.26,146.68 | 16.35,146.68 | R20.1 34.03,151.34 33.97,151.29 33.97,150.34 33.34,149.7 33.34,148.43 D5.2 | D4.2 45.56,149.7 46.04,150.18 46.04,150.97 46.09,151.03 R17.1 | 55.72,144.14 55.66,144.2 C14.1 | 46.2,144.14 55.72,144.14 | R16.1 57.63,144.14 55.72,144.14 | 43.34,140.33 43.34,132.87 43.97,132.24 | 50.16,135.73 50.11,135.67 R18.1 | R19.1 29.27,138.64 29.21,138.59 29.05,138.75 | v91.92,46.35 92.08,46.2 | D10.3 92.51,45.76 92.08,46.2 | 92.08,46.2 91.44,46.83 90.17,46.83 90.16,46.84 R45.1 | R44.2 104.2,21.53 104.14,21.59 104.04,21.49 R43.2 | 112.55,79.53 D1.8 111.28,79.53 110.81,79.06 110.81,78.1 | R3.1 109.53,76.35 109.54,76.36 109.54,76.35 110.81,76.35 | 110.81,76.35 R2.1 | 110.81,78.1 110.81,76.35 | v113.19,78.1 110.81,78.1 | 35.4,160.26 R59.1
  Bottom 0.254: D7.1 45.34,40.58 47.15,42.39 48.74,42.39 48.77,42.36 C26.1 | D7.9 46.04,36.51 46.51,36.04 46.51,34.77 48.1,33.18 48.9,33.18 | 48.9,33.18 | 48.9,33.18 C25.1 | D7.33 34.45,39.05 v34.13,38.73
  Bottom 0.305: 48.9,42.54 | 48.9,42.54 C26.1 | v48.9,44.29 48.9,42.54 | 48.9,42.54 | 48.9,33.18 50.64,33.18 v51.12,32.7
  Bottom 0.508: 54.77,163.99 55.56,163.99 X2.35 X2.33 60.64,165.58 98.11,165.58 X2.1 104.46,163.99 106.05,162.4 106.05,161.29 | 54.77,163.99 53.5,165.26 | 53.5,165.26 54.77,163.99 | 102.87,156.21 103.19,155.89 103.19,152.88 98.58,148.27 91.12,148.27 71.75,128.9 65.72,128.9 58.74,121.92 58.74,114.14 60.01,112.87 v60.01,111.12 60.01,107.47 61.12,106.36 v93.5,106.36 95.57,106.36 | 102.87,156.21 v102.71,156.37 | v57.63,111.12 57.63,106.04 57.55,105.97 56.52,104.93 v56.52,101.52 v56.52,82.07 X1.35 | v74.3,17.78 | 74.14,17.94 v74.3,17.78 | C47.1 69.08,17.01 v69.06,16.99 | 81.63,12.89 | v83.66,14.92 81.63,12.89 | 16.35,146.68 13.34,146.68 12.54,147.48 12.54,156.84 v15.95,160.26 35.4,160.26 47.23,160.26 50.16,157.32 53.02,157.32 | 33.34,148.43 33.34,145.26 32.28,144.2 C15.1 28.47,144.2 26.51,142.24 26.51,138.75 | D4.2 45.56,144.78 46.2,144.14 46.2,143.19 43.34,140.33 | 43.97,129.38 43.97,132.24 | 43.97,129.38 46.2,129.38 50.16,133.35 50.16,135.73 | R21.1 38.2,129.75 38.58,129.38 | 38.58,129.38 43.97,129.38 | 38.58,129.38 29.05,129.38 26.51,131.92 | 26.51,131.92 v18.26,131.92 11.75,131.92 10.32,133.35 10.32,161.45 10.32,161.92 13.65,165.26 53.5,165.26 | 26.51,131.92 26.51,138.75 | 26.51,138.75 29.05,138.75 | 53.02,157.32 X3.36 | 54.77,163.99 54.77,159.07 53.02,157.32 | X3.36 | X3.36 | 102.87,156.21 | v102.71,156.37 | 102.87,156.21 v102.71,156.37 | 106.05,161.29 | 106.05,161.29 L2.1 | 95.6,106.49 97.03,106.49 102.55,100.96 111.44,100.96 118.43,93.98 118.43,79.85 | 118.43,79.85 117.32,78.74 X6.3 | X6.3 | R44.2 106.62,21.53 v106.68,21.59 | C50.1 96.48,38.78 v97.79,37.46 | v114.94,16.99 118.43,20.48 v118.43,67.47 118.43,79.85
  Bottom 0.61: 106.05,161.29 | L2.1 106.05,161.29 | 106.05,161.29 105.89,161.45 | 95.57,106.36 95.57,106.52 95.6,106.49 C7.1
+3.3V_VGA  (via drill 0.51)
  Top 0.203: v82.71,114.3
  Top 0.305: 86.84,118.59 v82.71,114.3 | 86.84,118.59 86.36,119.06 v86.36,123.98 v86.36,138.43 | v92.23,122.55 90.96,122.55 86.84,118.59
  Bottom 0.203: D3.29 86.07,123.7 86.2,123.82 | 86.2,123.82 86.52,123.82 86.58,123.76 D3.30 86.58,123.76 v86.36,123.98 86.2,123.82 | 82.14,115.79 D3.13 | 88.9,138.59 | 88.9,138.59 C8.1 | 88.9,138.59 88.74,138.43 | 106.2,151.76 106.05,151.76 | 106.2,151.76 C10.1 | 106.2,151.76 | 98.58,122.55 | 98.58,122.55 C11.1 | v92.23,122.55 94.46,122.55 | 94.46,122.55 96.52,122.55 | 96.52,122.55 98.58,122.55 | 98.58,122.55 | 94.46,122.55 94.46,122.4 | 94.46,122.4 C12.1 | 94.46,122.4 | C13.1 96.52,122.4 C13.1 | 96.52,122.55 C13.1
  Bottom 0.305: 88.9,138.59 88.9,141.45 89.85,142.4 98.74,142.4 98.58,142.24 98.58,142.08 98.58,140.18 | 82.14,115.79 81.92,115.57 81.92,114.78 82.39,114.3 v82.71,114.3 | 88.74,138.43 v86.36,138.43 | 98.58,140.18 | 98.58,140.18 D2.14
  Bottom 0.508: 106.05,157.32 | 106.05,157.32 L2.2 | 106.05,154.94 106.05,157.32 | 106.05,157.32
  Bottom 0.61: C9.+ 106.36,154.62 106.05,154.94 106.05,151.92 | 106.05,151.92 | 106.05,151.92 106.05,151.76 106.05,149.54 98.58,142.08
+5V  (via drill 0.51)
  Top 0.254: X7.5 77.1,103.24 v77.31,103.03 77.6,103.32 X7.6
  Bottom 0.508: v77.31,103.03 | 85.72,99.38 79.85,99.38 77.31,101.92 v77.31,103.03
  Bottom 0.762: N1.3 87.25,89.75 85.72,91.28 85.72,99.38 86.52,100.17 87.95,100.17 C6.+ 87.91,102.67 87.95,102.71 | 87.95,102.71 | 87.95,102.71 C5.1
+5V_AUDIO  (via drill 0.7)
  Top 0.254: v33.66,44.29 27.78,38.42 12.38,38.42 11.59,37.62 11.59,37.31 16.19,32.7 13.97,30.48 13.97,29.21 16.03,27.15 25.56,27.15 27.94,24.76 v27.94,20.8
  Top 0.61: v39.05,47.47 36.83,47.47 v33.66,44.29 32.54,43.18 32.54,32.38 v33.81,31.11 | v33.81,31.11
  Bottom 0.254: D7.25 34.51,34.99 34.29,34.77 34.29,31.43 | v33.81,31.11 34.29,31.43 | 34.29,31.43 | C30.1 34.35,31.38 34.29,31.43 | D7.38 37.4,43.88 36.99,44.29 35.56,44.29 | 35.56,44.29 C29.1 | v33.66,44.29 35.56,44.29 | R35.2 26.83,19.68 v27.94,20.8 R40.2
  Bottom 0.61: N2.3 37.41,52.6 37.62,52.39 C20.+ 37.74,49.88 37.94,49.69 | 37.94,49.69 | 37.94,49.69 C19.1 | 37.94,49.69 37.94,48.58 v39.05,47.47
AUDIO-SCLK
  Bottom 0.254: 73.03,145.89 52.23,125.09 52.23,75.09 | 50.32,37.46 47.47,37.46 46.9,38.04 D7.6 | 52.23,75.09 52.23,54.77 55.09,51.91 59.21,51.91 60.01,51.12 60.01,34.45 58.42,32.86 53.5,32.86 51.12,35.24 51.12,36.67 50.32,37.46 | 52.23,75.09 | 50.32,37.46 | X3.21 | X3.21 73.03,155.1 73.03,145.89 | 73.03,145.89
AUDIO-SDI  (via drill 0.6)
  Top 0.254: 73.82,152.24 v74.3,152.24 73.82,152.24 | X3.24 71.75,153.19 72.71,152.24 73.82,152.24 | 73.82,152.24
  Bottom 0.254: D7.8 46.32,37.02 47.15,36.19 47.15,35.08 47.78,34.45 50.8,34.45 53.02,32.23 58.58,32.23 60.64,34.29 60.64,51.43 59.53,52.55 55.4,52.55 52.86,55.09 52.86,124.78 74.3,146.21 v74.3,152.24
AUDIO-SDO  (via drill 0.6)
  Top 0.254: v71.75,150.97 74.61,150.97 75.56,151.92 75.56,154.46 76.83,155.73 X3.19 | X3.19
  Bottom 0.254: D7.5 47.34,38.54 47.78,38.1 50.48,38.1 51.75,36.83 51.75,35.4 53.66,33.5 58.26,33.5 59.37,34.61 59.37,50.64 58.74,51.28 54.77,51.28 51.59,54.45 51.59,125.41 71.75,145.57 v71.75,150.97
AUDIO-SYNC
  Bottom 0.254: D7.10 45.59,36 45.88,35.72 45.88,34.61 47.31,33.18 47.31,32.23 47.94,31.59 58.74,31.59 61.28,34.13 61.28,51.75 59.85,53.18 55.72,53.18 53.5,55.4 53.5,74.45 53.5,124.46 | X3.22 | X3.22 75.56,152.56 75.56,146.53 53.5,124.46 | 53.5,124.46
AUX_IN_L
  Bottom 0.254: R32.2 45.24,22.7 44.13,21.59 36.35,21.59 35.56,22.38 35.56,24.45 X13.6
AUX_IN_R
  Bottom 0.254: X13.5 36.99,23.18 37.15,23.02 40.01,23.02 40.48,23.49 40.48,24.13 | 40.48,24.13 R29.2 | 40.48,24.13
BLUETOOTH_RX  (via drill 0.6)
  Top 0.203: D8.RX v61.91,89.69
  Bottom 0.203: D9.3 74.14,25.24 74.14,31.59 81.76,39.21 81.76,46.51 62.87,65.56 62.87,88.74 v61.91,89.69 | v61.91,89.69
BLUETOOTH_TX  (via drill 0.6)
  Top 0.203: D8.TX v61.91,87.15
  Bottom 0.203: v61.91,87.15 61.91,74.93 60.33,73.34 60.33,68.74 61.59,67.47 61.59,65.88 81.12,46.2 81.12,39.37 73.66,31.91 73.66,24.61 D9.2 | D9.2 75.56,22.7 | D9.2
BOARD_GPAD0  (via drill 0.51, 0.76)
  Top 0.203: X19.1
  Top 0.254: v78.26,43.5 78.26,48.74 83.66,54.13 83.8,54.28 X18.P$4 | X19.1 44.61,6.98 53.18,15.56 v67.31,15.56
  Bottom 0.203: D9.61 72.87,14.13
  Bottom 0.254: 72.87,14.13 68.74,14.13 66.83,16.03 | 66.83,16.03 66.83,28.57 78.26,40 v78.26,43.5 | v67.31,15.56 66.83,16.03
BOARD_GPAD1  (via drill 0.51, 0.76)
  Top 0.203: X19.2
  Top 0.254: v77.31,44.77 77.31,48.89 82.71,54.29 82.8,54.39 X18.P$3 | X19.2 47.15,7.62 53.66,14.13 53.82,14.29 v67.15,14.29
  Bottom 0.203: D9.60 77.11,17.34 73.1,13.33
  Bottom 0.254: 68.1,13.33 73.1,13.33 | v67.15,14.29 68.1,13.33 | v67.15,14.29 66.2,15.24 66.2,29.21 77.31,40.32 v77.31,44.77 | v67.15,14.29 68.1,13.33
BOARD_GPAD2  (via drill 0.51, 0.76)
  Top 0.203: X19.3
  Top 0.254: v76.2,46.04 76.2,48.89 81.44,54.13 81.8,54.5 X18.P$2 | v66.99,13.02 54.61,13.02 54.29,12.7 49.69,8.1 49.69,6.03 X19.3
  Bottom 0.203: D9.59 77.67,16.79 73.42,12.54
  Bottom 0.254: 67.47,12.54 73.42,12.54 | 67.47,12.54 65.56,14.45 65.56,29.84 76.2,40.48 v76.2,46.04 | v66.99,13.02 | v66.99,13.02 67.47,12.54
BOARD_GPAD3  (via drill 0.51, 0.76)
  Top 0.203: X19.4
  Top 0.254: v74.93,47.31 74.93,48.89 80.8,54.77 80.8,63.5 X18.P$1 | X19.4 52.23,8.41 55.56,11.75 v66.83,11.75
  Bottom 0.203: D9.58 73.82,11.75
  Bottom 0.254: v66.83,11.75 73.82,11.75 | v66.83,11.75 64.93,13.65 64.93,30.48 74.93,40.48 v74.93,47.31 | v66.83,11.75 66.36,12.22 | 66.36,12.22 v66.83,11.75 | v66.83,11.75 66.36,12.22
BOARD_GPIO0
  Bottom 0.203: X17.1 84.14,4.6 80.64,8.1 80.64,10.79 82.21,12.36 | 82.21,12.36 82.23,12.38 | 82.21,12.36 D9.51
BOARD_GPIO1
  Bottom 0.203: X17.2 82.39,7.14 81.28,8.25 81.28,10.32 82.74,11.77 D9.50
BOARD_GPIO2
  Bottom 0.203: X17.3 | X17.3 88.9,5.87 88.9,7.78 88.27,8.41 82.23,8.41 81.76,8.89 81.76,9.68 83.32,11.25 | 83.32,11.25 83.34,11.27 | 83.32,11.25 D9.49
BOARD_GPIO3
  Bottom 0.203: X17.4 90.17,8.1 89.38,8.89 88.27,8.89 D9.48 | D9.48 85.88,11.27 | D9.48
BOARD_GPIO4
  Bottom 0.203: D9.47 86.5,11.76 88.74,9.52 90.49,9.52 91.44,8.57 91.44,5.87 X17.5 | X17.5
BOARD_GPIO5
  Bottom 0.203: D9.46 89.22,10.16 91.12,10.16 92.71,8.57 X17.6 | X17.6
BOARD_GPIO6
  Bottom 0.203: D9.45 87.61,12.87 89.69,10.79 91.76,10.79 93.98,8.57 93.98,5.87 X17.7 | X17.7
BOARD_GPIO7
  Bottom 0.203: D9.44 88.17,13.43 90.17,11.43 92.39,11.43 95.25,8.57 95.25,7.3 95.41,7.14 X17.8
BOARD_GPIO8
  Bottom 0.203: D9.35 93.18,18.42 95.09,16.51 97.63,16.51 105.41,8.73 X17.16 | X17.16
BOARD_GPIO9
  Bottom 0.203: D9.36 92.63,17.86 94.61,15.87 96.84,15.87 104.14,8.57 104.14,5.87 X17.15 | X17.15
BOARD_GPIO10
  Bottom 0.203: D9.37 92.07,17.31 94.14,15.24 96.2,15.24 102.87,8.57 X17.14 | X17.14
BOARD_GPIO11
  Bottom 0.203: D9.38 91.51,16.76 93.66,14.6 95.57,14.6 101.6,8.57 101.6,5.87 X17.13 | X17.13
BOARD_GPIO12
  Bottom 0.203: D9.39 90.95,16.2 93.19,13.97 94.93,13.97 100.33,8.57 X17.12 | X17.12
BOARD_GPIO13
  Bottom 0.203: D9.40 90.4,15.65 92.71,13.33 94.3,13.33 99.06,8.57 99.06,5.87 X17.11 | X17.11
BOARD_GPIO14
  Bottom 0.203: D9.41 89.84,15.09 92.23,12.7 93.66,12.7 97.79,8.57 X17.10 | X17.10
BOARD_GPIO15
  Bottom 0.203: D9.42 89.28,14.54 91.76,12.06 93.03,12.06 96.52,8.57 96.52,5.87 X17.9 | X17.9
BOARD_HV_SCL
  Bottom 0.203: 83.66,49.05 | 83.66,49.05 107.79,73.18 108.11,73.5 R3.2 | 83.66,49.05 83.66,38.73 75.56,30.64 75.56,27.15 77.75,24.96 | 77.75,24.96 77.79,24.92 | D9.6 77.75,24.96 | D1.7 112.39,80.8 113.67,80.8 114.3,80.17 114.3,76.04 113.19,74.93 110.81,74.93 R3.2 | R3.2
BOARD_HV_SDA
  Bottom 0.203: 76.04,27.78 76.04,30.32 84.3,38.58 84.3,48.74 107.31,71.6 111.12,71.6 112.24,72.71 112.24,73.34 R2.2 113.03,73.5 114.94,75.41 114.94,81.91 113.51,83.34 112.55,83.34 D1.5 | 76.04,27.78 | D9.7 78.29,25.53 76.04,27.78
BOARD_LCDON  (via drill 0.51)
  Top 0.203: 79.53,102.71 78.74,101.92 78.74,100.96 79.53,100.17 79.53,89.85 68.58,78.9 | 79.53,102.71 | 79.53,102.71 79.6,102.78 X7.10 | 68.58,78.9 | v67.94,67.15 67.94,78.26 68.58,78.9
  Bottom 0.203: 83.03,49.37 83.03,38.89 75.09,30.96 75.09,26.51 77.18,24.42 D9.5 | 83.03,49.37 | 83.03,49.37 | 83.03,49.37 82.71,49.69 80.8,49.69 67.94,62.55 v67.94,67.15
BOARD_RX  (via drill 0.51)
  Top 0.203: v72.39,23.81 72.71,23.81 82.71,33.81 86.84,33.81 94.3,26.35 94.3,25.4 v94.3,24.76 | P10.PP 7.62,120.17 8.57,119.22 22.86,119.22 31.27,127.63 58.26,127.63 v59.21,126.68 | v59.21,126.68
  Bottom 0.203: 57.63,67.79 56.36,67.79 55.24,68.9 55.24,122.71 58.58,126.05 v59.21,126.68 81.92,149.54 81.92,151.92 80.64,153.19 80.64,155.1 X3.17 | 57.63,67.79 79.85,45.56 79.85,45.4 | 79.85,45.4 | 79.85,45.4 79.85,39.69 72.71,32.54 72.71,24.13 v72.39,23.81 | D9.28 92.07,24.44 92.39,24.76 | v94.3,24.76 93.19,24.76 93.03,24.92 92.55,24.92 92.39,24.76 | 92.39,24.76 | 57.63,67.79 | X3.17
BOARD_SCL  (via drill 0.76)
  Top 0.203: v110.17,24.76 110.17,33.5 109.22,34.45 107.95,34.45 107.94,34.43 X21.P$18
  Bottom 0.203: D9.25 90.54,26.09 90.54,26.25 91.44,27.15 94.14,27.15 98.11,23.18 104.3,23.18 R44.1 108.64,23.23 v110.17,24.76
BOARD_SDA  (via drill 0.76)
  Top 0.203: X21.P$19 109.12,33.43 109.54,33.02 109.54,25.72 108.74,24.92 v108.74,21.11
  Bottom 0.203: D9.26 90.95,25.55 91.92,26.51 93.82,26.51 100.49,19.84 102.08,19.84 | 102.08,19.84 | 102.08,19.84 R43.1 102.08,19.84 | v108.74,21.11 107.47,19.84 102.08,19.84 | 102.08,19.84
BOARD_TCK
  Bottom 0.203: X20.1 66.36,8.57 68.74,10.95 74.14,10.95 78.86,15.67 D9.57
BOARD_TDI
  Bottom 0.203: D9.54 80.52,14 76.52,10 X20.9
BOARD_TDO
  Bottom 0.203: X20.3 | X20.3 70.17,5.71 72.07,5.71 72.71,6.35 72.71,8.41 73.66,9.37 74.77,9.37 79.98,14.58 | 79.98,14.58 80.01,14.6 | 79.98,14.58 D9.55
BOARD_TMS
  Bottom 0.203: D9.56 74.61,10.32 72.87,10.32 71.44,8.89 X20.5
BOARD_TX  (via drill 0.51)
  Top 0.203: v73.34,22.7 74.3,23.81 74.3,24.76 82.87,33.34 86.68,33.34 87.63,32.38 | 87.63,32.38 | 87.63,32.38 93.03,26.83 93.19,26.67 93.19,25.88 v93.03,25.72 | P9.PP 21.11,120.49 29.69,129.06 56.52,129.06 58.74,129.06 v59.53,128.27
  Bottom 0.203: 57.94,126.68 54.77,123.51 54.77,68.58 56.04,67.31 56.99,67.31 79.22,45.24 79.22,39.85 72.23,32.86 72.23,24.76 | 72.23,24.76 71.6,24.13 71.6,23.34 72.23,22.7 v73.34,22.7 | 72.23,24.76 | D9.27 91.55,24.98 91.6,24.92 92.39,25.72 v93.03,25.72 | 57.94,126.68 | 57.94,126.68 v59.53,128.27 | X3.18 | X3.18 79.38,153.51 81.28,151.61 81.28,150.02 v59.53,128.27 | v59.53,128.27 | v59.53,128.27
BOARD_VGA  (via drill 0.51)
  Top 0.203: v92.55,120.65 92.39,120.49 89.53,120.49 84.14,115.09 84.14,114.46 v82.71,113.03 | v75.41,108.74 75.41,107.47 73.98,106.04 73.98,91.28 | 73.98,91.28 | 73.98,91.28 71.28,88.58 71.28,85.25 60.33,74.29 v60.33,67.15
  Bottom 0.203: D3.38 92.33,120.87 v92.55,120.65 100.17,120.65 100.65,120.17 R12.1 | v82.71,113.03 82.71,111.44 80.01,108.74 v75.41,108.74 | 60.33,66.04 v60.33,67.15 60.33,66.04 | 60.33,66.04 80.49,45.88 80.49,39.53 73.18,32.23 73.18,23.97 D9.1 | 60.33,66.04
CAP_DRDY  (via drill 0.51)
  Top 0.203: v104.78,43.97 104.78,42.7 102.87,41.12 97.47,41.12 94.3,37.94 85.25,37.94 81.12,33.81 v81.12,33.34
  Bottom 0.203: D10.21 100.9,46.26 102.39,44.77 104.78,44.77 | 104.78,44.77 105.09,44.77 105.73,44.13 106.52,44.13 | 106.52,44.13 | 106.52,44.13 R54.1 | v104.78,43.97 104.78,44.77 | 82.09,29.43 D9.14 82.21,29.39 | 82.21,29.39 82.23,29.37 | v81.12,33.34 81.12,30.48 82.21,29.39
CAP_MISO  (via drill 0.51)
  Top 0.203: v80.17,32.46 80.17,33.65 84.93,38.42 93.98,38.42 97.63,42.07 v99.69,42.07
  Bottom 0.203: D10.26 97.77,43.36 99.06,42.07 v99.69,42.07 | 81.62,28.87 D9.13 81.62,28.87 80.17,30.32 v80.17,32.46
CAP_MOSI  (via drill 0.51)
  Top 0.203: v100.97,42.86 97.79,42.86 93.66,38.89 84.61,38.89 79.22,33.5 v79.22,31.51
  Bottom 0.203: D10.25 98.27,43.65 98.9,42.86 v100.97,42.86 | 81.06,28.32 D9.12 81.09,28.28 | 81.09,28.28 81.12,28.26 | v79.22,31.51 79.22,30.16 80.01,29.37 | 80.01,29.37 | 81.09,28.28 80.01,29.37
CAP_SCLK  (via drill 0.51)
  Top 0.203: 100.17,43.34 97.47,43.34 93.5,39.37 84.3,39.37 78.42,33.5 78.26,33.34 v78.26,30.56 | 100.17,43.34 100.25,43.34 | v103.03,43.34 102.39,43.97 100.97,43.97 100.33,43.34 100.17,43.34
  Bottom 0.203: 80.51,27.76 D9.11 80.51,27.76 79.38,28.89 | v78.26,30.56 78.26,30 79.38,28.89 | 79.38,28.89 | D10.23 100.15,45.26 101.44,43.97 102.39,43.97 v103.03,43.34
GND  (via drill 0.51, 0.6, 0.7, 3.2)
  Top 0.203: v96.68,46.51 94.93,46.51 93.98,47.47 93.98,50.96 v93.5,51.43 | v35.24,100.81 40.32,95.73 v57.78,95.73 | v20,153.51 16.67,153.51 14.13,156.05 9.21,156.05 7.78,157.48 P8.PP 6.99,157.48 5.24,155.73 5.24,136.21 | P12.PP 5.24,117.47 4.13,118.59 4.13,135.1 5.24,136.21 | 29.69,140.49 v29.84,140.49 | 7.46,133.98 | 7.46,133.98 P19.PP | 5.24,136.21 7.46,133.98 | v93.5,51.43 | X21.P$1 106.2,51.43 105.89,51.12 105.89,46.51 105.89,43.5 | 105.89,39.37 105.89,36.04 106.52,35.4 107.79,35.4 X21.P$17 | 105.89,41.91 105.89,39.37 | 105.89,43.5 105.89,41.91 | X21.P$13 105.95,39.43 105.89,39.37 | X21.P$9 105.95,43.43 105.89,43.5 | 105.89,41.91 v105.41,41.91
  Top 0.254: X7.1 75.1,103.49 v75.72,102.87 75.6,102.99 X7.2 | X7.12 80.6,101.87 v80.17,101.44 | 94.1,103.5 94.1,103.47 v93.66,103.03 | 94.1,103.5 X7.39 | 94.1,103.5 94.14,103.5 94.6,103.97 X7.40 | v42.86,22.54 42.86,21.59 35.24,21.59 34.29,22.54 X13.3 | X13.3
  Top 0.305: v50.8,52.39 v63.98,52.39
  Top 0.508: X1.34 59.05,66.83 67.94,57.94 67.94,21.11 v69.37,19.68 v80.49,19.68 99.54,19.68 101.6,21.75 101.6,31.27 v98.58,34.29 | 58.9,161.45 57.78,161.45 57.78,164.94 58.42,165.58 98.11,165.58 | 58.9,161.45 X2.34 | 58.9,161.45 X2.36 54.77,161.45 | v25.4,140.49 29.69,140.49 v51.91,140.49 | v51.12,158.91 52.23,158.91 54.77,161.45 | 23.65,152.72 22.86,153.51 v20,153.51 | v11.43,161.29 11.43,163.04 13.65,165.26 53.5,165.26 54.77,163.99 54.77,161.45 | v57.78,84.61 D8.GND | X3.3 | X3.3 X3.1 X2.2 98.42,162.72 98.42,165.26 98.11,165.58 | X3.3 | v109.38,165.26 109.06,165.58 98.11,165.58 | v88.42,42.07 v93.34,42.07 96.68,45.4 v96.68,46.51 105.89,46.51 | 105.89,46.51
  Top 0.61: X1.36 v47.94,70.01 | v23.18,44.61 23.18,43.18 21.59,41.59 8.1,41.59 6.35,43.34 v6.35,44.45 | v18.1,55.72 v18.1,59.37 | v19.05,66.04 19.05,65.72 18.1,64.77 18.1,59.53 | v12.06,35.24 12.38,35.24 v14.45,33.18 | v14.45,33.18
  Bottom 0.203: 108.27,44.13 R54.2 108.17,43.24 107.63,42.7 105.41,42.7 | v96.68,46.51 97.43,45.76 D10.22 100.6,45.76 102,44.37 103.27,44.37 103.98,43.66 103.98,43.18 104.46,42.7 105.41,42.7 | v96.68,46.51 | X20.2 66.36,3.02 66.83,2.54 75.88,2.54 76.52,3.17 X20.10 | X20.10 | R55.2 93.72,51.65 v93.5,51.43 | 95.42,35.23 95.41,35.24 95.73,35.24 | 95.42,35.23 C49.1 | 99.29,31.36 C48.1 | 97.31,33.34 95.42,35.23 | X20.10 | X20.10 78.26,6.19 78.26,10.64 81.07,13.44 D9.53 81.09,13.47 | D9.63 | v88.42,42.07 88.45,42.1 89.98,42.1 91.12,40.96 C55.2 91.25,40.99 91.28,40.96 | X9.14 25,100.09 25.72,100.81 30,100.81 30.04,100.77 X9.SW | X9.3 28.55,114.59 27.62,113.66 27.62,107.16 | 27.62,107.16 28.42,107.16 29.84,107.16 29.85,107.15 X9.6 | X9.SW 28.92,100.77 27.62,102.08 27.62,107.16 | X9.SW 35.21,100.77 v35.24,100.81 | D6.P$1 20.12,151.48 20,151.29 19.88,151.48 20.16,151.13 21.43,151.13 21.79,151.48 D6.P$50 | v20,153.51 19.84,153.67 v20,153.51 23.81,153.51 25.03,154.72 R22.2 27.46,154.62 | D5.10 39.69,140.18 37.47,142.4 29.84,142.4 C15.2 v29.84,140.49 | 51.91,138.91 52.07,138.75 51.93,138.61 D4.10 v51.91,140.49 | 29.9,154.72 29.84,154.78 | 29.9,154.72 R23.2 27.57,154.72 27.46,154.62 | 29.9,154.72 R24.2 | 29.9,154.72 | 27.46,154.62 | 12.06,1.59 3.49,1.59 3.49,4.29 4.6,5.4 | 4.6,5.4 | 4.6,5.4 7.3,5.4 10.48,8.57 11.11,8.57 | R5.2 103.82,82.87 104.29,83.33 D1.4 | v105.41,41.91 105.41,42.7 | 94.14,40.64 94.16,40.62 C50.2
  Bottom 0.254: 43.97,39.05 | 43.97,39.05 D7.4 | 43.97,39.05 47.15,39.05 47.65,39.56 C26.2 50.3,39.56 52.39,37.46 52.39,35.72 53.98,34.13 57.94,34.13 58.74,34.92 58.74,43.02 v57.63,43.02 | 48.9,35.88 | 48.9,35.88 C25.2 | 48.9,35.88 48.74,36.04 48.1,36.04 46.61,37.53 D7.7 42.64,37.53 42.55,37.62 | 21.91,45.72 | 21.91,45.72 C21.1 | 21.91,44.61 C22.1 | 21.91,44.61 21.91,45.72 | 15.88,44.61 R26.1 | 21.91,44.61 15.88,44.61 | 15.88,45.88 R25.1 15.88,44.61 | 43.97,39.05 42.55,39.05 42.55,37.62 | 42.55,37.62 42.55,37.46 | 36.83,35.56 36.77,35.5 D7.26 33.91,35.5 33.66,35.24 33.66,32.54 32.54,31.43 32.23,31.43 32.17,31.38 C39.2 31.91,31.43 31.85,31.38 C41.2 29.84,31.27 29.69,31.43 27.94,31.43 | 36.83,35.56 39.05,37.78 39.21,37.78 | 39.21,37.78 v41.91,37.78 42.39,37.78 42.55,37.62 | D7.42 39.43,38 39.21,37.78 | 15.08,58.9 R27.1 15.08,57.78 | 15.08,56.83 | R28.1 15.08,56.83 | 15.08,56.83 15.08,57.78 | C28.2 17.25,57.89 17.14,57.78 15.08,57.78 | 29.37,36.19 29.31,36.25 C43.1 26.51,36.35 | 26.51,36.35 26.51,31.91 26.99,31.43 27.94,31.43 | 27.94,31.43 27.88,31.38 C40.2 | R37.2 20.48,35.88 | X14.4 | X14.3 15.56,24.45 | 15.56,24.45 X14.4 | X14.4 | C45.- 25.24,24.92 24.77,24.45 15.56,24.45 | R31.2 42.12,29.74 41.75,29.37 41.75,26.99 43.97,26.99 43.97,24.45 43.66,24.13 43.02,24.13 42.97,24.07 R30.2 v42.86,22.54 | C30.2 35.56,33.65 36.83,34.92 36.83,35.56 | C29.2 35.56,41.91 36.83,40.64 36.83,35.56 | 26.51,38.42 26.51,36.35 | 26.51,39.53 26.51,38.42 | C42.1 26.51,38.42 | C37.2 57.63,45.88 v57.63,43.02 | 57.63,40 | 57.63,40 C38.2 | v57.63,43.02 57.63,40 | v75.72,102.87 | 20.48,34.77 | v17.78,34.77
  Bottom 0.305: X14.3 15.56,24.45 v9.68,24.45 v6.35,24.45 | X11.3 15.56,51.12 | v6.35,51.12 v9.68,51.12 15.56,51.12 | X11.4 15.56,51.12 | 34.29,18.89 45.24,18.89 48.74,22.38 48.74,29.05 49.21,29.53 59.21,29.53 63.18,33.5 63.18,48.58 63.98,49.37 v63.98,52.39 | 34.29,18.89 | 12.7,0.95 16.51,0.95 17.78,0.95 19.05,2.22 19.05,3.65 34.29,18.89 | 50.8,63.5 | 50.8,63.5 | 50.8,63.5 v50.8,52.39 | 12.06,1.59 12.54,1.11 12.7,0.95 | 12.7,0.95 | v6.35,44.45 | v6.35,44.45 6.27,44.53
  Bottom 0.406: C46.2 16.51,2.38 16.51,0.95
  Bottom 0.457: X2.34 57.78,161.45 | X2.36 57.78,161.45 | 57.78,161.45 57.78,156.37 | X3.33 | 57.78,156.37 X3.33 | X3.35 | 57.78,156.37 X3.35
  Bottom 0.508: v109.38,165.26 110.65,163.99 110.65,161.45 | 75.72,105.25 80.17,105.25 | 80.17,105.25 90.17,105.25 | 90.17,105.25 | 75.72,105.25 v75.72,102.87 | 58.9,105.25 57.78,104.14 v57.78,95.73 v57.78,84.61 57.78,70.01 57.63,70.01 | 57.63,70.01 X1.36 | 57.63,70.01 X1.34 | 97.31,33.34 99.29,31.36 | D9.63 76.36,19.84 77.79,19.84 79.22,18.41 | 79.22,18.41 82.23,15.4 82.23,14.6 81.09,13.47 | 71.6,19.68 | 71.6,19.68 C47.2 | v69.37,19.68 71.6,19.68 | 97.31,33.34 95.41,35.24 | 97.47,33.34 97.31,33.34 | 97.47,33.34 107.95,33.34 | 79.22,18.41 v80.49,19.68 88.64,27.68 D9.22 | v20,153.51 20,153.19 20,151.29 | C14.2 53.92,142.5 v51.91,140.49 | v25.4,140.49 25.4,134.46 23.97,133.03 12.54,133.03 11.43,134.14 11.43,152.72 v11.43,161.29 | v11.43,161.29 | 99.54,88.9 99.71,89.07 | V3.2 107.48,88.26 108.43,87.31 | 108.43,87.31 110.65,87.31 111.28,87.95 111.25,87.98 C2.2 111.12,87.95 111.23,88.05 R6.2 115.2,88.05 115.25,88.11 R7.2 | D1.4 107.62,83.33 108.43,84.14 108.43,87.31 | C3.- 87.79,85.09 89.38,86.68 89.53,86.84 89.53,87.47 | 80.17,105.25 v80.17,101.44 | 90.17,105.25 90.94,104.49 C5.2 90.96,102.71 | 90.96,102.71 | 90.96,102.71 91.16,102.51 C6.- 91.16,99.41 89.53,97.79 89.53,95.57 | 94.14,40.48 94.16,40.5 C50.2 | v93.34,42.07 93.34,41.27 94.14,40.48 | 94.14,40.48 94.14,38.73 95.73,37.15 95.73,35.08 95.63,35.18 C49.1 | v98.58,34.29 98.42,34.29 97.47,33.34 | X3.1 | X3.1 101.44,154.62 101.44,152.72 98.11,149.38 90.49,149.38 71.44,130.02 65.41,130.02 57.63,122.24 57.63,113.51 58.82,112.32 58.82,105.33 58.9,105.25 | 58.9,105.25 58.82,105.25 | 58.9,105.25 75.72,105.25 | 58.9,105.25
  Bottom 0.61: 110.65,161.45 | 110.65,161.45 L3.1 | 20.48,34.77 20.48,35.88 | 20.48,34.77 R38.2 | 20.48,34.77 v17.78,34.77 16.03,34.77 v14.45,33.18 | v6.35,31.11 | v6.35,31.11 6.35,33.5 6.35,35.32 | v6.35,37.78 6.35,42.23 v6.35,44.45 | 6.35,35.32 v6.35,37.78 | v6.35,44.45 | v6.35,44.45 | v6.35,44.45 6.35,48.58 | 6.35,48.58 v6.35,51.12 6.35,62.07 | 6.35,62.07 6.35,63.5 8.89,66.04 33.34,66.04 36.26,63.12 N2.4 39.69,53.66 40.96,52.39 | v6.35,17.78 | v6.35,17.78 6.35,20.16 6.35,22.07 | v6.35,31.11 | 6.35,22.07 v6.35,24.45 v6.35,31.11 | v6.35,17.78 | 6.35,12.38 v6.35,17.78 | C19.2 40.77,52.2 40.96,52.39 | 40.96,52.39 | 40.96,52.39 C20.- | 34.29,23.34 | 34.29,23.34 X13.3 | 34.29,23.34 X13.4 34.29,22.22 v28.26,16.19 v25.72,16.19 v23.5,13.97 19.37,13.97 16.35,10.95 7.78,10.95 6.35,12.38 | 34.29,23.34 | v6.35,37.78 v9.68,37.78 12.06,37.78 14.13,39.85 26.19,39.85 26.51,39.53 | 6.35,12.38 | 49.05,66.04 | 49.05,66.04 C18.2 | 50.64,66.04 49.05,66.04 | 50.8,63.5 C17.- | 50.8,63.5 | 50.8,63.5 50.8,65.88 50.64,66.04 | 50.64,66.04 50.64,70.01 v47.94,70.01 | v47.94,70.01 | X10.GND 6.35,48.65 6.35,48.58 | 23.97,44.77 24.13,44.77 24.29,44.61 v23.18,44.61 21.91,44.61 | X12.GND 6.44,61.98 6.35,62.07 | R28.1 15.98,56.57 16.83,55.72 v18.1,55.72 | X16.GND 6.44,21.98 6.35,22.07 | 6.35,35.32 6.43,35.32 6.44,35.31 X15.GND 9.91,35.31 10,35.4 10.16,35.24 v12.06,35.24 | 20.48,34.77 v23.34,34.77 | 15.56,24.45
  Bottom 0.762: 89.53,87.47 N1.4 89.53,95.57 | C7.2 94.33,103.69 v93.66,103.03 93.34,102.71 C5.2
  Bottom 1.016: 99.54,88.9 | 99.54,88.9 C1.- 99.54,88.9 | 99.54,88.9 99.69,88.74 | 99.54,88.9 99.54,101.6 97.63,103.5 95.73,103.5 95.57,103.66 | 99.71,89.07 105.4,89.07 105.41,89.06 107.31,89.06 107.33,89.07 V3.2 | X4.1 105.41,75.09 103.98,73.66 101.76,73.66 97.95,77.47 97.95,83.5 99.85,85.57 99.85,88.9 99.69,89.06 99.54,88.9 | C3.- 87.75,84.97 87.82,84.9 C4.2
  other vias: 3.02,65.72 6.35,65.72 9.68,66.04 13.02,66.04 24.45,63.98 30,66.04 34.45,64.93 34.61,62.23 34.61,59.37 34.61,56.36 30.8,59.69 30.8,55.09 34.61,53.34 34.61,50.16 24.45,59.85 24.45,55.72 24.61,51.59 28.42,49.21 31.59,46.2 27.15,41.27 24.61,39.85 20.48,39.85 15.88,39.85 6.35,57.78 9.68,10.95 15.4,10.95 18.57,13.18 32.86,20.8 27.15,35.4 19.53,28.73 37.47,35.56 38.42,40 21.91,10.95 46.67,60.48 46.67,55.24 50.8,60.48 50.8,55.24 46.67,50.16 42.23,44.45 45.72,43.5 50.64,47.94 54.13,42.86 41.91,39.37 57.47,35.56 65.56,48.1 65.56,40.16 65.56,32.38 55.88,27.78 51.75,23.5 46.67,17.78 37.15,17.78 42.55,12.86 32.54,12.86 27.46,7.46 37.15,7.3 31.59,2.22 22.38,2.22 19.53,7.3 66.67,66.04 64.14,66.2 76.36,66.04 72.87,66.04 76.36,57.63 83.82,52.39 84.61,66.04 80.49,66.04 88.74,66.04 92.87,61.91 92.87,66.04 88.74,57.63 96.84,66.04 97.31,57.63 95.09,55.4 101.6,61.91 105.73,66.04 107.79,61.91 117.16,66.04 117.16,61.91 117.16,53.97 117.16,46.51 117.16,38.73 117.32,2.38 111.28,2.38 117.32,8.73 116.36,13.49 111.28,8.73 105.41,14.13 115.41,27.3 112.24,27.3 80.49,23.02 88.42,22.86 88.42,19.68 84.61,26.51 41.43,2.22 48.1,2.22 54.77,2.22 61.44,2.22 61.44,9.21 57.15,9.21 56.99,17.78 62.87,23.49 69.53,23.49 69.53,40.16 69.53,48.1 61.44,60.32 61.44,57.31 57.47,60.48 57.47,57.31 64.77,57.31 68.1,54.13 3.02,70.01 30,70.01 9.68,70.01 36.51,70.01 16.03,70.01 42.23,70.01 3.02,77.95 9.68,77.95 16.03,77.95 30,77.95 23.34,77.95 36.51,77.95 42.23,77.95 47.78,77.79 47.78,86.04 3.02,93.66 9.68,93.66 16.03,93.66 23.34,93.66 30,93.66 36.51,93.66 42.23,93.66 50.17,93.98 3.02,103.35 9.68,103.35 16.03,103.35 23.34,103.35 3.02,110.97 9.68,110.97 16.03,110.97 23.34,110.97 9.68,120.49 23.34,118.59 16.03,125.41 9.68,125.41 23.34,125.41 1.91,125.41 1.91,118.74 1.91,133.19 1.91,142.72 1.91,149.7 1.91,157.8 1.91,164.94 9.05,164.94 5.56,161.29 15.4,162.72 18.73,162.72 27.46,162.72 33.02,162.72 38.1,162.72 42.86,162.72 47.94,162.72 40.64,158.11 45.4,158.11 45.4,154.46 51.12,154.46 27.46,151.45 42.39,150.65 36.99,150.65 36.51,143.51 20.32,138.91 23.97,138.91 23.97,136.84 42.39,143.51 54.77,150.65 49.69,150.65 64.14,150.65 66.67,150.65 61.28,137 54.93,139.86 26.19,124.14 54.77,130.18 41.91,125.41 36.67,125.41 31.43,125.41 50.8,119.7 46.04,121.44 45.4,113.51 49.69,113.51 49.69,107.32 45.4,107.32 39.37,107.32 66.83,103.66 71.91,103.66 71.91,98.11 66.83,98.11 66.83,91.44 71.91,91.44 66.83,86.68 76.52,98.11 76.52,91.44 69.53,66.04 101.44,98.11 101.44,91.44 98.27,86.04 107.95,86.04 101.44,94.93 98.58,101.12 117,98.42 117,103.66 113.35,103.66 108.58,103.66 102.87,106.2 61.59,151.61 58.9,150.65 61.44,143.35 65.72,141.29 68.42,143.99 61.12,119.86 71.91,80.8 77.31,86.2 77.31,82.87 71.91,77.63 72.71,61.91 109.22,69.53 117.16,74.93 85.72,159.54 75.56,159.54 80.64,159.54 85.72,157.96
  pour Bottom (no thermals): 39.21,38.42 40.96,38.42 40.96,37.31 39.21,37.31
  pour Bottom (no thermals): 40.8,40.8 42.7,40.8 42.7,35.4 40.96,37.15 40.8,37.31
  pour Bottom (no thermals): 36.67,40.8 39.53,40.8 39.53,37.15 41.91,34.77 36.67,34.77
  pour Bottom: 0,9.68 23.02,9.68 28.57,15.24 28.58,15.24 34.13,20.8 44.61,20.8 46.83,23.02 46.83,29.84 39.53,37.15 39.53,45.08 42.7,48.26 42.7,66.83 0,66.83
  pour Top: 0,9.68 23.02,9.68 28.57,15.24 28.58,15.24 34.13,20.8 44.61,20.8 46.83,23.02 46.83,29.84 39.53,37.15 39.53,45.08 42.7,48.26 42.7,66.83 0,66.83
  pour Bottom: 0,8.57 0,0 32.7,0 64.61,31.91 64.77,51.91 63.02,53.66 55.88,53.66 54.61,54.93 54.61,67.31 44.13,67.31 44.13,48.1 40.64,44.61 40.64,37.46 47.94,30.16 47.94,22.7 45.09,19.84 34.45,19.84 23.18,8.57
  pour Top: 0,8.57 0,0 32.86,0 64.77,31.91 64.77,51.91 63.02,53.66 55.88,53.66 54.61,54.93 54.61,54.93 54.61,67.31 44.13,67.31 44.13,48.1 40.64,44.61 40.64,37.46 47.94,30.16 47.94,22.7 45.09,19.84 34.45,19.84 23.18,8.57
